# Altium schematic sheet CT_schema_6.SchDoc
size 260 x 245 mm
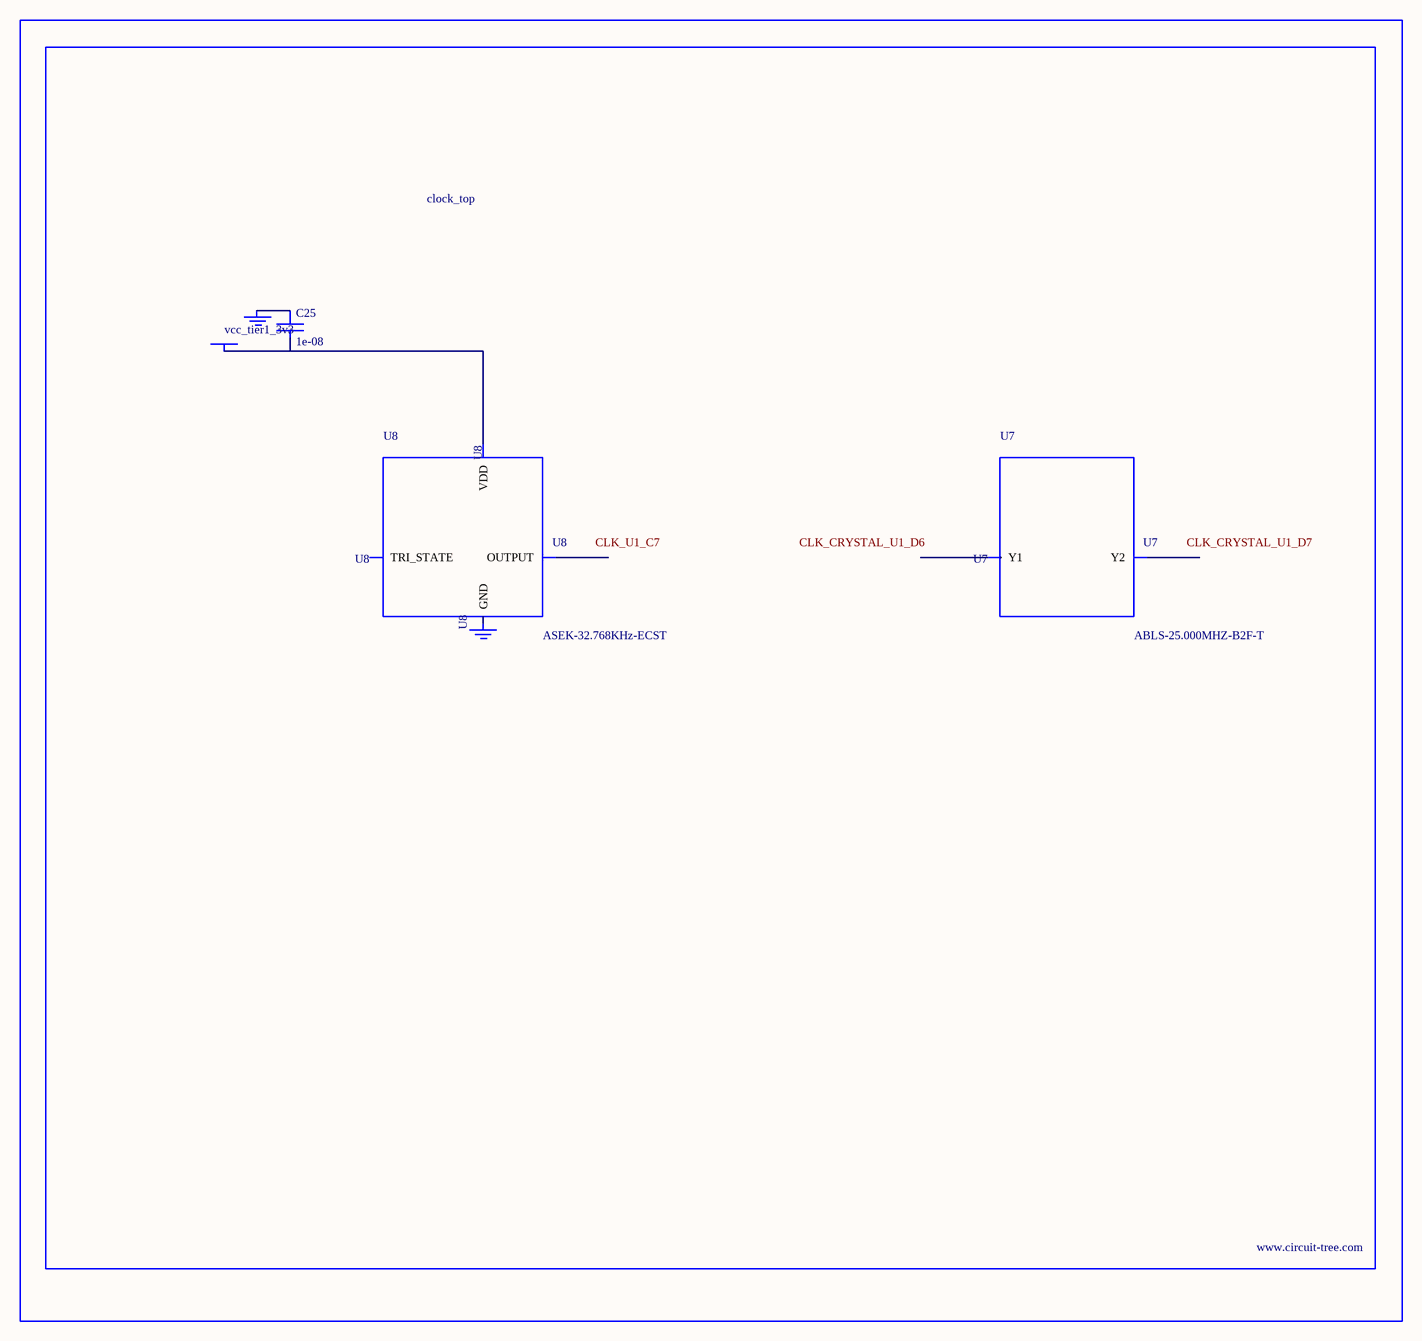
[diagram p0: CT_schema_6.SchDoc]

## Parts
BORDER5  (no value)
C25  1e-08  [C0402]
GND_INSTANCE_5_0  (no value)
GND_INSTANCE_5_1  (no value)
POWER_INSTANCE_5_0  vcc_tier1_3v3
U7  ABLS-25.000MHZ-B2F-T  [ABLS-25.000MHZ-B2F-T]
U8  ASEK-32.768KHz-ECST  [ASEK]

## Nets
NetC25_1: C25.1 GND_INSTANCE_5_0.0(GND)
NetC25_2: C25.2 POWER_INSTANCE_5_0.0(PWR) U8.4(VDD)

Not connected (* = marked no-connect by the designer): GND_INSTANCE_5_1 0(GND); U7 1(Y1) 2(Y2); U8 1(TRI_STATE) 2(GND) 3(OUTPUT)

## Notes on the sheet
- Labels drawn without touching a wire or pin: CLK_CRYSTAL_U1_D6, CLK_CRYSTAL_U1_D7, CLK_U1_C7

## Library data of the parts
BORDER5 = BORDER_PAGE5
C25 = C0402C103K3RAC
GND_INSTANCE_5_0 GND_INSTANCE_5_1 = GND
POWER_INSTANCE_5_0 = PWR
